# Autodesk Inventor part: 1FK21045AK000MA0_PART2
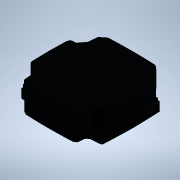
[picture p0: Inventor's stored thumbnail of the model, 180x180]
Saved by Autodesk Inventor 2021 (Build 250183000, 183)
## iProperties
Created: 2025-04
Part Number: 1FK21045AK000MA0_PART2
Material: Generic
Catalog Web Link: www.3dfindit.com
Description: -Servo synchronous motor
Document SubType Name: Modeling
Designer: psAdmin
Mass: 135.825 g
Surface Area: 188.795 cm^2
Volume: 135.825 cm^3
Density: 1 g/cm^3
Appearance: PSOLRGB-38-46-56
Category: PARTsolutions
Title: 1FK21045AK000MA0_PART2
Author: Cadenas PARTsolutions
Comments: Servo synchronous motor
Sending System: PARTsolutions
Preprocessor: ST-DEVELOPER v19.3
PSOL_IDENT_0: {$CADENAS_DATA/23d-libs/siemens_ag/_cat_/3d/2f/1fk21045ak000ma0.prj},213 {VTYP=3D},{NB=1FK21045AK000
PSOL_IDENT_1: MA0_PART2},{LINA=1FK21045AK000MA0_PART2},{NN=1FK21045AK000MA0_PART2},{NOPRJ=TRUE},{DATE=19.08.2025 1
PSOL_IDENT_2: 4:00:34},{GEOMDATE=30.07.2025 02:01:24},{VERSION=},{LINEID=10},{WBVAR=},{WBNUMERIC=}  {NB=1FK21045AK
PSOL_IDENT_3: 000MA0_PART2},{LINA=1FK21045AK000MA0_PART2},{KT=DUMMY},{PREVIEW=../../../_pool_/a9/69/p_d211_xx_0081
PSOL_IDENT_4: 8j.png},{DESCSHORT=SIMOTICS S-1FK2 HD, SINAMICS S210 3AC 400V-480V, 1.7 Nm, 6000 rpm},{DESCLONG=SIMO
PSOL_IDENT_5: TICS S-1FK2 HD servo motor M0=2.4 Nm; PN = 1.07 kW at nN=6000 rpm (380-480 V); PN = 0.75 kW at nN=30
PSOL_IDENT_6: 00 rpm (200-240 V); degree of protection IP64; cylindrical shaft D19x40mm; absolute encoder 22-bit +
PSOL_IDENT_7: 12-bit multiturn (encoder AM22DQC); with OCC interface; plug size M17, rotatable; SIMOTICS S-1FK2 s
PSOL_IDENT_8: ervomotorfor a wide range of uses in industrial environments. SIMOTICS S‑1FK2 servomotors are compac
PSOL_IDENT_9: t synchronous motors with a high dynamic performance that set themselves apart as a result of their
PSOL_IDENT_10: high power density, degree of protection and overload capability. The motors are available in two va
PSOL_IDENT_11: riants: as High Dynamic variant (highest dynamic performance as a result of the low intrinsic moment
PSOL_IDENT_12: of inertia for applications demanding a high dynamic performance with low moved masses) - and as Co
PSOL_IDENT_13: mpact variant (precise and stable closed-loop control for medium up to large moved masses as a resul
PSOL_IDENT_14: t of a medium intrinsic moment of inertia). SIMOTICSS‑1FK2 servomotors fully exploit their strengths
PSOL_IDENT_15: in a system with the SINAMICSS210 frequency converter and simple connection using the one cable con
PSOL_IDENT_16: nection (OCC). Advantages include the short control and positioning times, fast and precise correcti
PSOL_IDENT_17: on of disturbing quantities as well as stable control with a high dynamic performance. The servo mot
PSOL_IDENT_18: ors can be configured to address a wide range of requirements. For example with and without holding
PSOL_IDENT_19: brake, IP64 or IP65 degree of protection, singleturn or multiturn absolute encoders - to name just a
PSOL_IDENT_20: few. Further, the servomotors are available in different shaft heights extending from 20 to 100. A
PSOL_IDENT_21: shaft sealing ring is available to achieve an IP65 degree of protection and for subsequent mounting
PSOL_IDENT_22: at the motor or as spare part. SIMOTICS - the optimum motor for each and every motion control applic
PSOL_IDENT_23: ation.},{INTNO=804766789342},{SUPPLIERALTNO=1FK2104-5AK00-0MA0},{MANUID=1FK21045AK000MA0},{MANUNAME=
PSOL_IDENT_24: Siemens},{MANUTYPEDESC=Synchronous motor 1FK2-HD 2,39 Nm},{AAU732=SIMOTICS},{AAO057=S-1FK2},{AAU734=
PSOL_IDENT_25: SIMOTICS S-1FK2 HD servo motor M0=2.4 Nm; PN = 1.07 kW at nN=6000 rpm (380-480 V); PN = 0.75 kW at n
PSOL_IDENT_26: N=3000 rpm (200-240 V); degree of protection IP64; cylindrical shaft D19x40mm; absolute encoder 22-b
PSOL_IDENT_27: it + 12-bit multiturn (encoder AM22DQC); with OCC interface; plug size M17, rotatable;},{AAW338=Sync
PSOL_IDENT_28: hronous motor 1FK2-HD 2,39 Nm},{AAO742=SIMOTICS},{AAO663=4042948691151},{NOCUPEROU=1},{PRICEQUANTITY=
PSOL_IDENT_29: 1},{QUANTITYMIN=1},{QUANTITYINT=1},{CTN=85015100},{COO=DE},{AAO676=1FK2104-5AK00-0MA0},{AAO677=Sieme
PSOL_IDENT_30: ns AG},{ORDERUNIT=C62},{CONTENTUNIT=C62}
NB: 1FK21045AK000MA0_PART2
NT: Servo synchronous motor
NBSYN: $MANUID._PART2
LINA: 1FK21045AK000MA0_PART2
CATALOG: SIEMENS
PREVIEW: ../../../_pool_/a9/69/p_d211_xx_00818j.png
DESCSHORT: SIMOTICS S-1FK2 HD, SINAMICS S210 3AC 400V-480V, 1.7 Nm, 6000 rpm
DESCLONG: SIMOTICS S-1FK2 HD servo motor M0=2.4 Nm; PN = 1.07 kW at nN=6000 rpm (380-480 V); PN = 0.75 kW at nN=3000 rpm (200-240 V); degree of protection IP64; cylindric
INTNO: 804766789342
SUPPLIERALTNO: 1FK2104-5AK00-0MA0
MANUID: 1FK21045AK000MA0
MANUNAME: Siemens
MANUTYPEDESC: Synchronous motor 1FK2-HD 2,39 Nm
AAU732: SIMOTICS
AAO057: S-1FK2
AAU734: SIMOTICS S-1FK2 HD servo motor M0=2.4 Nm; PN = 1.07 kW at nN=6000 rpm (380-480 V); PN = 0.75 kW at nN=3000 rpm (200-240 V); degree of protection IP64; cylindric
AAW338: Synchronous motor 1FK2-HD 2,39 Nm
AAO742: SIMOTICS
AAO663: 4042948691151.0
NOCUPEROU: 1
PRICEQUANTITY: 1
QUANTITYMIN: 1
QUANTITYINT: 1
CTN: 85015100
COO: DE
ARTICLENO: 1FK21045AK000MA0_PART2
BOMINFO: 1FK21045AK000MA0_PART2
CREATOR: CADENAS GmbH
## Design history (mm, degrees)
feature "2025_04_17_15_39_51_0603"
body "Solid1"
